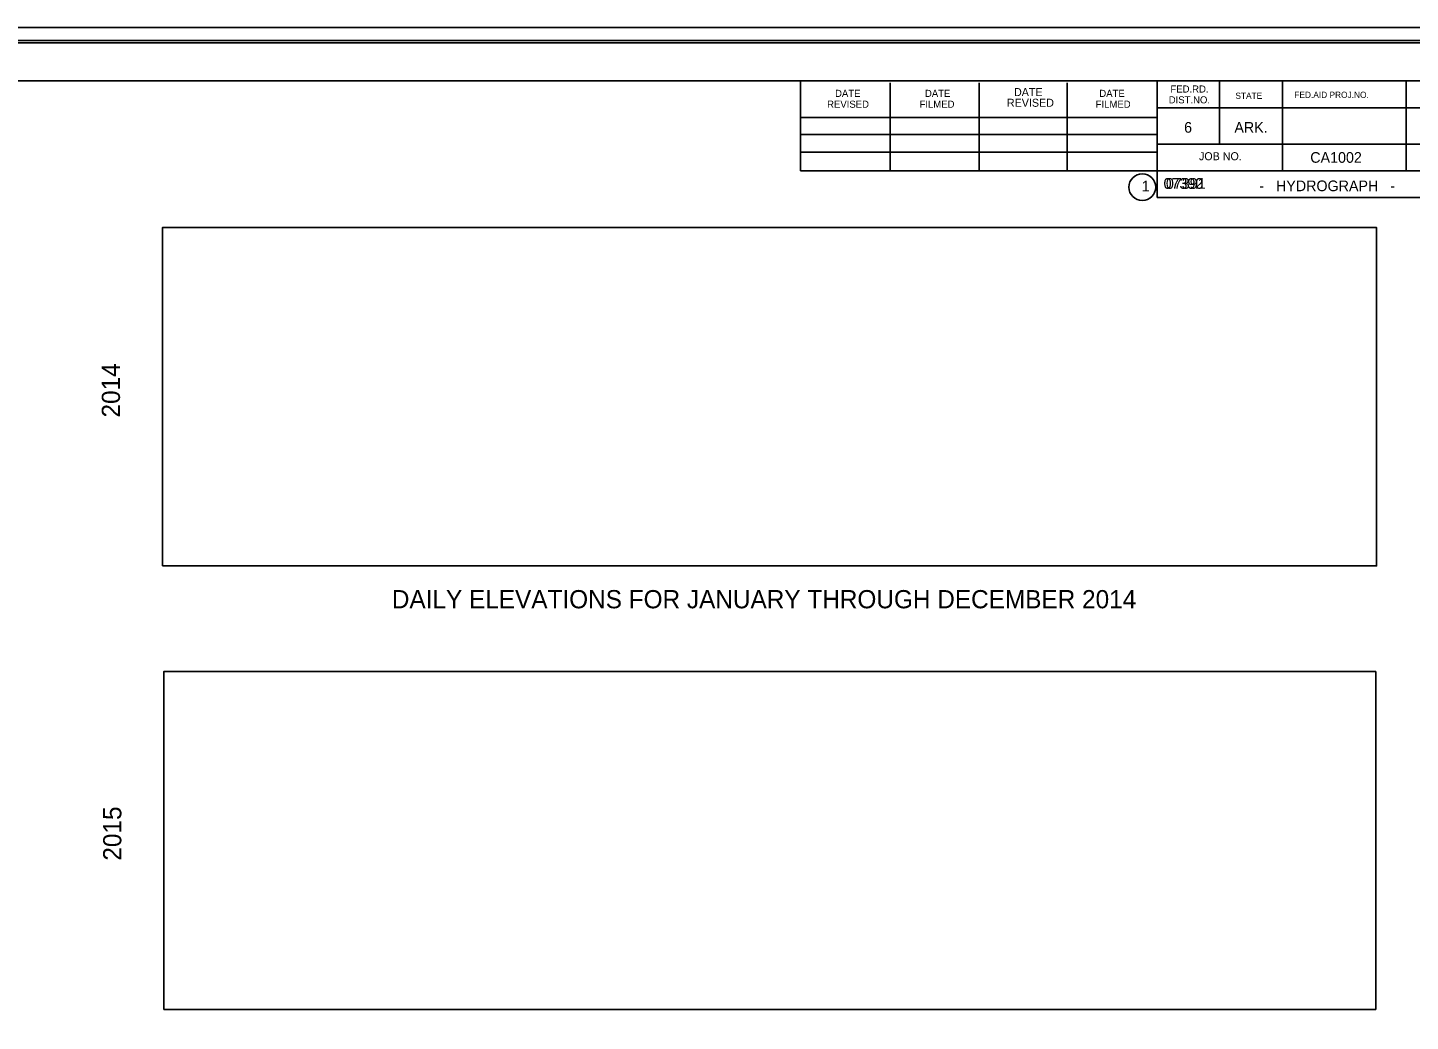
# Model space of a CAD drawing. Extents: x -1063117.9 to -1063075.9, y -253323.6 to -253301.6.
# Drawn here: x -1063100.86 to -1063085.67, y -253312.54 to -253301.63 of the extents above; entities that cross this region are included whole.
import ezdxf

# ---------------------------------------------------------------- set-up
doc = ezdxf.new("R2010")
doc.units = 0
for name, color, linetype in [('border', 7, 'Continuous'), ('Border 2660-Hwy18 - Level 62', 7, 'Continuous'), ('Border 2660-Hwy18 - Level 63', 7, 'Continuous'), ('Border 2660-Hwy18 - Text', 7, 'Continuous'), ('Bridge No BLFR', 7, 'Continuous'), ('Bridge No BLO', 7, 'Continuous'), ('Bridge No Ditch 81', 7, 'Continuous'), ('Dimensions', 7, 'Continuous'), ('Level 62 PDF', 7, 'Continuous'), ('Title Text', 7, 'Continuous')]:
    doc.layers.add(name, color=color, linetype=linetype)

msp = doc.modelspace()

# ---------------------------------------------------------------- linework, layer by layer
at = {"layer": 'border'}
for p, q in [((-1063116.157, -253302.216), (-1063084.146, -253302.216)), ((-1063092.372, -253303.204), (-1063092.372, -253302.216)), ((-1063091.387, -253303.204), (-1063091.387, -253302.235)), ((-1063090.41, -253303.204), (-1063090.41, -253302.235)), ((-1063089.443, -253303.204), (-1063089.443, -253302.235)), ((-1063088.456, -253302.216), (-1063088.456, -253303.495)), ((-1063087.772, -253302.216), (-1063087.772, -253302.91)), ((-1063087.078, -253302.216), (-1063087.078, -253303.204)), ((-1063085.72, -253302.216), (-1063085.72, -253303.204)), ((-1063084.146, -253302.51), (-1063088.456, -253302.51)), ((-1063092.372, -253302.618), (-1063088.456, -253302.618)), ((-1063092.372, -253302.804), (-1063088.456, -253302.804)), ((-1063092.372, -253303.204), (-1063092.372, -253302.997)), ((-1063092.372, -253302.997), (-1063088.456, -253302.997)), ((-1063084.146, -253302.91), (-1063088.456, -253302.91)), ((-1063088.16, -253302.91), (-1063084.146, -253302.91)), ((-1063084.146, -253303.204), (-1063092.372, -253303.204)), ((-1063088.456, -253303.495), (-1063084.146, -253303.495))]:
    msp.add_line(p, q, dxfattribs=at)
msp.add_circle((-1063088.618, -253303.382), 0.147, dxfattribs=at)
at = {"layer": 'Border 2660-Hwy18 - Level 62'}
msp.add_lwpolyline([(-1063117.777, -253301.63), (-1063083.659, -253301.63), (-1063083.659, -253323.44), (-1063117.777, -253323.44)], close=True, dxfattribs=at)
at = {"layer": 'Border 2660-Hwy18 - Level 63'}
msp.add_lwpolyline([(-1063117.888, -253301.773), (-1063083.889, -253301.773), (-1063083.889, -253323.143), (-1063117.888, -253323.143)], close=True, dxfattribs=at)
at = {"layer": 'Dimensions'}
for points in [[(-1063099.378, -253307.541), (-1063086.045, -253307.541), (-1063086.045, -253303.825), (-1063099.378, -253303.825)], [(-1063099.363, -253312.41), (-1063086.054, -253312.41), (-1063086.054, -253308.701), (-1063099.363, -253308.701)]]:
    msp.add_lwpolyline(points, close=True, dxfattribs=at)
at = {"layer": 'Level 62 PDF'}
msp.add_lwpolyline([(-1063117.527, -253301.797), (-1063083.409, -253301.797), (-1063083.409, -253323.607), (-1063117.527, -253323.607)], close=True, dxfattribs=at)

# ---------------------------------------------------------------- texts
at = {"layer": 'Border 2660-Hwy18 - Text'}
for s, height, p in [('DATE', 0.0782, (-1063091.992, -253302.391)), ('DATE', 0.0782, (-1063091.005, -253302.391)), ('DATE', 0.0879, (-1063090.027, -253302.382)), ('DATE', 0.0782, (-1063089.09, -253302.391)), ('DIST.NO.', 0.0782, (-1063088.328, -253302.462)), ('FED.RD.', 0.0782, (-1063088.309, -253302.343)), ('STATE', 0.0684, (-1063087.596, -253302.412)), ('FED.AID PROJ.NO.', 0.06839, (-1063086.949, -253302.402)), ('REVISED', 0.0782, (-1063092.079, -253302.51)), ('FILMED', 0.0782, (-1063091.064, -253302.51)), ('REVISED', 0.0879, (-1063090.105, -253302.499)), ('FILMED', 0.0782, (-1063089.13, -253302.51)), ('6', 0.117, (-1063088.159, -253302.784)), ('ARK.', 0.1172, (-1063087.607, -253302.784)), ('JOB NO.', 0.0879, (-1063087.996, -253303.086)), ('CA1002', 0.1172, (-1063086.774, -253303.114)), ('1', 0.117, (-1063088.625, -253303.429))]:
    msp.add_text(s, height=height, dxfattribs=at).set_placement(p)
at = {"layer": 'Bridge No BLFR'}
msp.add_text('07392', height=0.1172, dxfattribs=at).set_placement((-1063088.385, -253303.4))
at = {"layer": 'Bridge No BLO'}
msp.add_text('07391', height=0.1172, dxfattribs=at).set_placement((-1063088.359, -253303.4))
at = {"layer": 'Bridge No Ditch 81'}
msp.add_text('07390', height=0.1172, dxfattribs=at).set_placement((-1063088.384, -253303.4))
at = {"layer": 'Title Text'}
for s, height, p in [('-   HYDROGRAPH   -', 0.11722, (-1063087.333, -253303.426)), (' DAILY ELEVATIONS FOR JANUARY THROUGH DECEMBER 2014 ', 0.2, (-1063096.933, -253308.006))]:
    msp.add_text(s, height=height, dxfattribs=at).set_placement(p)
for s, p in [('2014', (-1063099.844, -253305.911)), ('2015', (-1063099.829, -253310.777))]:
    msp.add_text(s, height=0.2, rotation=90, dxfattribs=at).set_placement(p)

doc.saveas('drawing.dxf')
